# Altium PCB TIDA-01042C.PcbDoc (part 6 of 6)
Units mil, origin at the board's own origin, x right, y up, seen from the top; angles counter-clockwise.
Board outline 8300 x 7100 mil, 8 copper layers (Top Layer, Signal Layer 1, Signal Layer 2, Signal Layer 3, Signal Layer 4, Signal Layer 5, Signal Layer 6, Bottom Layer), stack 59.2 mil thick; 551 components, 303 nets, 1611 pads, 2322 vias.
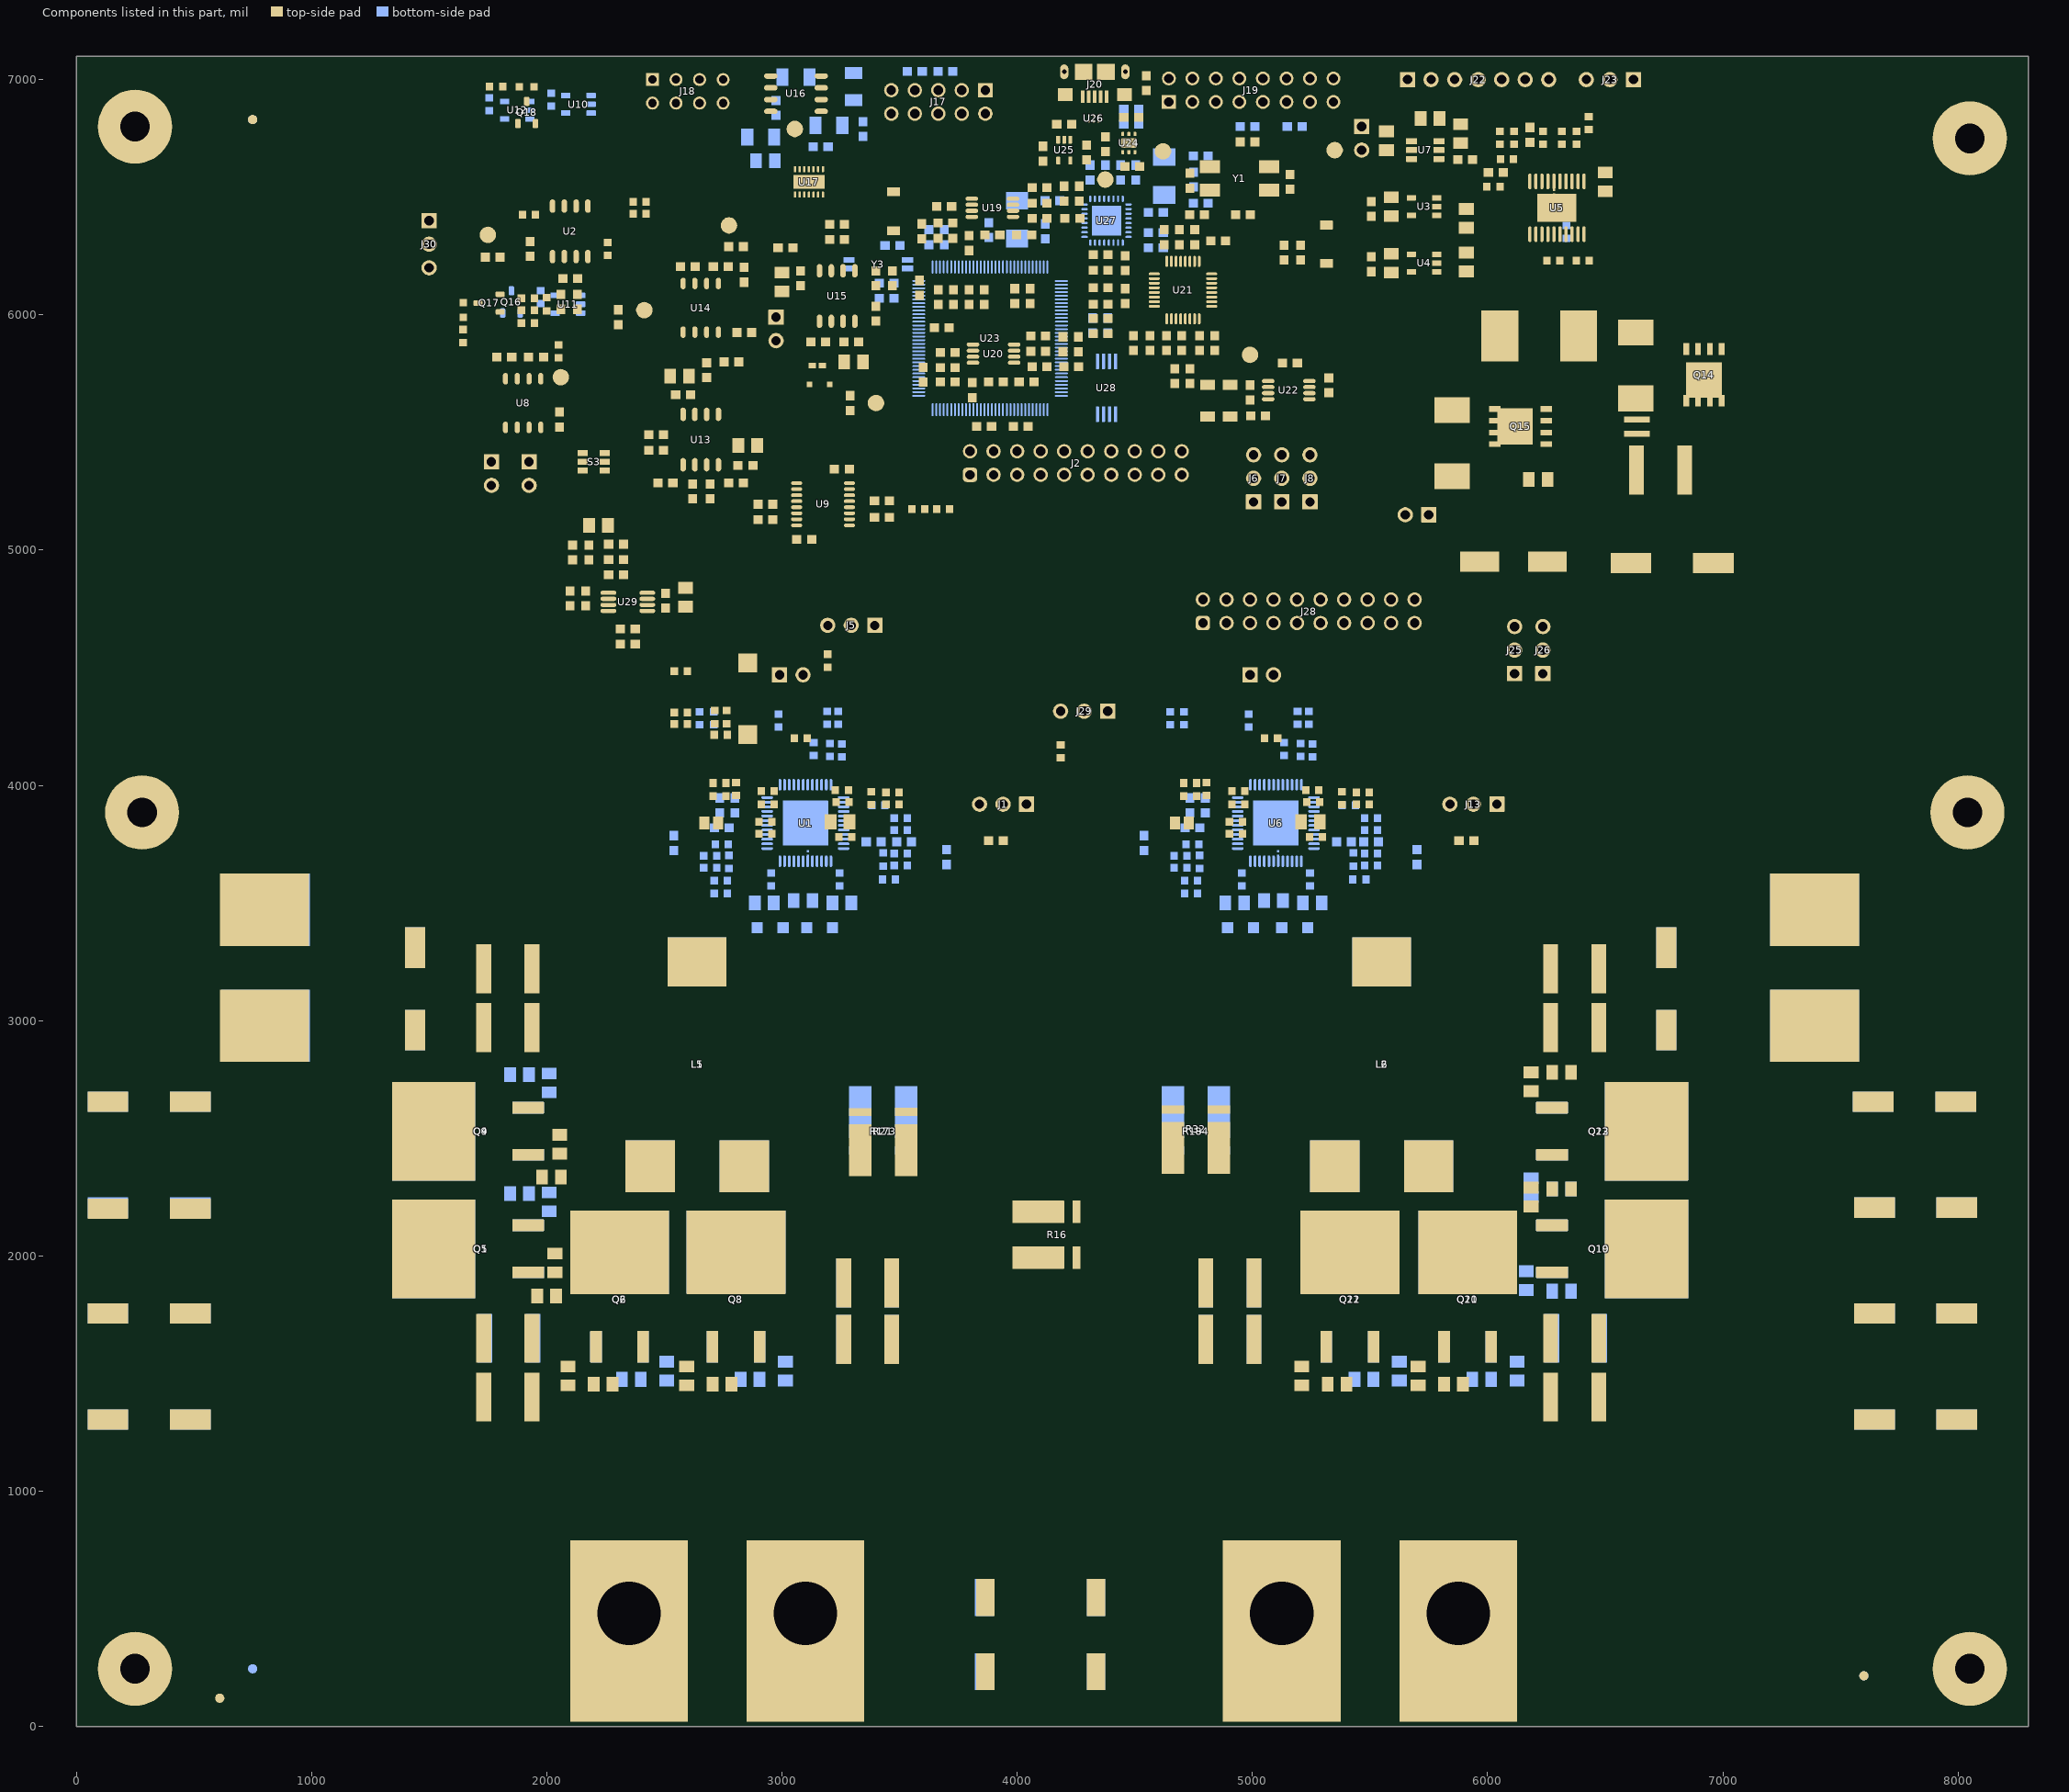
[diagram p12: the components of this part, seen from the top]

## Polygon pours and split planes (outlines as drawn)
V_HV on Bottom Layer "V_HV_L08_P6363" (solid, remove dead copper, pour order 6363): 7845,1090 6365,1090 6365,3125 7845,3125
V_HV on Bottom Layer "V_HV_L08_P6364" (solid, remove dead copper, pour order 6364): 1840,1095 335,1095 335,3130 1840,3130
I_TOTAL on Bottom Layer "I_TOTAL_L08_P6361" (solid, remove dead copper, pour order 6361): 4730,2090 3460,2090 3460,2815 4730,2815
PGND on Bottom Layer "PGND_L08_P6367" (solid, remove dead copper, pour order 6367): 1.9,0 1.9,7129.1 8321.9,7129.1 8321.9,0
AGND on Bottom Layer "AGND_L08_P6365" (solid, remove dead copper, pour order 6365): 2469.97,7080 1425,7080 1425,3650 6615,3650 6615,7080
V_LV on Bottom Layer "V_LV_L08_P6362" (solid, remove dead copper, pour order 6362): 5465.14,25.26 4829.74,25.26 4445,410 3750,410 3423.14,736.86 3423.14,2050 4888.14,2050 4888.14,1315 5465.14,738
AGND on Bottom Layer "AGND_L08_P6355" (solid, remove dead copper, pour order 6355): 4739.81,3520 4739.81,4004.81 4895,4160 5465,4160 5465,3565 5590,3565 5590,4270 4615,4270 4615,3520
AGND on Bottom Layer "AGND_L08_P6356" (solid, remove dead copper, pour order 6356): 2739.81,3520 2739.81,4004.81 2895,4160 3465,4160 3465,3565 3590,3565 3590,4270 2615,4270 2615,3520
SW4 on Bottom Layer "SW4_L08_P6359" (solid, remove dead copper, pour order 6359): 5520,2730 5520,2270 5483.67,2233.67 5103.67,2233.67 5070,2200 5070,1855 5111.33,1813.67 6313.67,1813.67 6350,1850 6350,2740 6316.33,2773.67 5563.67,2773.67
SW3 on Bottom Layer "SW3_L08_P6360" (solid, remove dead copper, pour order 6360): 3180,1855 3180,2185 3130,2235 2715,2235 2670.56,2279.44 2670.56,2714.44 2620,2765 1885,2765 1850.56,2730.56 1850.56,1879.44 1925,1805 3130,1805
NetL5_1 on Bottom Layer "NETL5_1_L08_P6357" (solid, remove dead copper, pour order 6357): 2720,2260 3370,2260 3395,2285 3395,2725 3370,2750 2720,2750 2700,2730 2700,2280
NetL6_2 on Bottom Layer "NETL6_2_L08_P6358" (solid, remove dead copper, pour order 6358): 4830,2250 5460,2250 5490,2280 5490,2730 5460,2760 4830,2760 4800,2730 4800,2280
I_TOTAL on Signal Layer 1 "I_TOTAL_L02_P6323" (solid, remove dead copper, pour order 6323): 4730,2090 3460,2090 3460,2815 4730,2815
V_LV on Signal Layer 1 "V_LV_L02_P6324" (solid, remove dead copper, pour order 6324): 3775,1860 4530,1860 4530,955 3775,955
PGND on Signal Layer 1 "PGND_L02_P6326" (solid, remove dead copper, pour order 6326): 0,0 0,7100 8300,7100 8300,0
AGND on Signal Layer 1 "AGND_L02_P6325" (solid, remove dead copper, pour order 6325): 2469.97,7080 1425,7080 1425,3650 6615,3650 6615,7080
V_LV on Signal Layer 2 "V_LV_L03_P6330" (solid, remove dead copper, pour order 6330): 5465.14,25.26 4829.74,25.26 4445,410 3750,410 3423.14,736.86 3423.14,2050 4888.14,2050 4888.14,1315 5465.14,738
I_TOTAL on Signal Layer 2 "I_TOTAL_L03_P6327" (solid, remove dead copper, pour order 6327): 4730,2085 3460,2085 3460,2810 4730,2810
V_LV on Signal Layer 2 "V_LV_L03_P6329" (solid, remove dead copper, pour order 6329): 3750,1855 4525,1855 4525,955 3750,955
PGND on Signal Layer 2 "PGND_L03_P6334" (solid, remove dead copper, pour order 6334): 0,0 0,7100 8300,7100 8300,0
AGND on Signal Layer 2 "AGND_L03_P6333" (solid, remove dead copper, pour order 6333): 2469.97,7080 1425,7080 1425,3650 6615,3650 6615,7080
V_HV on Signal Layer 2 "V_HV_L03_P6332" (solid, remove dead copper, pour order 6332): 7080,4800 6850,4800 6850,5105 6800,5155 6800,5500 6800,5525 6775,5550 6775,5820 7080,5820
V_HV on Signal Layer 2 "V_HV_L03_P6331" (solid, remove dead copper, pour order 6331): 7080,4800 6850,4800 6850,5105 6800,5155 6800,5500 6800,5525 6775,5550 6775,5820 7080,5820
PGND on Top Layer "PGND_L01_P6322" (solid, remove dead copper, pour order 6322): 1.9,0 1.9,7129.1 8321.9,7129.1 8321.9,0
AGND on Top Layer "AGND_L01_P6321" (solid, remove dead copper, pour order 6321): 2469.97,7080 1425,7080 1425,3650 6615,3650 6615,7080
V_LV on Top Layer "V_LV_L01_P6318" (solid, remove dead copper, pour order 6318): 5462,25.26 4824.74,25.26 4435,415 3745,415 3420,740 3420,2055 4885,2055 4885,1290 5462,713
NetC42_1 on Top Layer "NETC42_1_L01_P6308" (solid, remove dead copper, pour order 6308): 5715,4855 5715,5370 6200,5370 6200,5245 6200,5185 6070,5055 6065,5050 6065,4855
V_HV on Top Layer "V_HV_L01_P6312" (solid, remove dead copper, pour order 6312): 7050,4800 6870,4800 6850,4820 6850,5104.74 6799.74,5155 6799.74,5500 6799.74,5525 6774.74,5550 6774.74,5784.74 6810,5820 7050,5820 7079.74,5790.26 7079.74,4829.74
NetD6_2 on Top Layer "NETD6_2_L01_P6309" (solid, remove dead copper, pour order 6309): 6215,5430 6215.01,5729.99 6150,5795 6150,6015 6115,6050 6000,6050 5957.5,6007.5 5957.5,5822.5 5935,5800 5790,5800 5750,5760 5750,5430 5780,5400 6185,5400
NetC41_1 on Top Layer "NETC41_1_L01_P6307" (solid, remove dead copper, pour order 6307): 6295,5810 6295,6020 6330,6055 7060,6055 7080,6035 7080,5865 7055,5840 6800,5840 6740,5780 6705,5780 6325,5780
SW1 on Top Layer "SW1_L01_P6317" (solid, remove dead copper, pour order 6317): 3180,1840 3180,2200 3143.26,2236.74 2716.74,2236.74 2670,2283.49 2670,2750 2653.26,2766.74 1886.74,2766.74 1850,2730 1850,1845 1888.26,1806.74 3146.74,1806.74
NetL1_2 on Top Layer "NETL1_2_L01_P6313" (solid, remove dead copper, pour order 6313): 2720,2270 3370,2270 3395,2295 3395,2735 3370,2760 2720,2760 2700,2740 2700,2290
V_HV on Top Layer "V_HV_L01_P6320" (solid, remove dead copper, pour order 6320): 1840,1095 335,1095 335,3130 1840,3130
V_HV on Top Layer "V_HV_L01_P6319" (solid, remove dead copper, pour order 6319): 7845,1090 6365,1090 6365,3125 7845,3125
SW2 on Top Layer "SW2_L01_P6316" (solid, remove dead copper, pour order 6316): 5520,2730 5520,2280 5473.67,2233.67 5108.67,2233.67 5070,2195 5070,1860 5116.33,1813.67 6308.67,1813.67 6350,1855 6350,2740 6316.33,2773.67 5563.67,2773.67
NetL2_1 on Top Layer "NETL2_1_L01_P6314" (solid, remove dead copper, pour order 6314): 4830,2260 5460,2260 5490,2290 5490,2740 5460,2770 4830,2770 4800,2740 4800,2290
DGND on Top Layer "DGND_L01_P6311" (solid, remove dead copper, pour order 6311): 4155,7025 4150,7020 4150,6610 4280,6610 4265,6595 4265,6285 4275,6275 4535,6275 4535,6585 4570,6620 4570,7025 4170,7025 4165,7030
DGND on Top Layer "DGND_L01_P6310" (solid, remove dead copper, pour order 6310): 4150,7000 4150,6600 4250,6600 4250,6250 4500,6250 4500,6495 4575,6495 4570,6500 4570,7000
I_TOTAL on Top Layer "I_TOTAL_L01_P6315" (solid, remove dead copper, pour order 6315): 4730,2090 3460,2090 3460,2815 4730,2815
I_TOTAL on Signal Layer 3 "I_TOTAL_L04_P6335" (solid, remove dead copper, pour order 6335): 4730,2090 3460,2090 3460,2815 4730,2815
V_LV on Signal Layer 3 "V_LV_L04_P6338" (solid, remove dead copper, pour order 6338): 3770,1855 4520,1855 4520,955 3770,955
AGND on Signal Layer 3 "AGND_L04_P6340" (solid, remove dead copper, pour order 6340): 2469.97,7080 1285,7080 1285,3650 6615,3650 6615,7080
PGND on Signal Layer 3 "PGND_L04_P6341" (solid, remove dead copper, pour order 6341): 5797.48,7075 7280,7075 7280,3545 0,3545 0,7075 2472.33,7075 1485,7075 1485,5485 2487.75,5485 3627.33,4345.42 3630.03,4348.12 4646.91,4348.12 4646.91,4350 5795.11,5498.19
V_HV on Signal Layer 3 "V_HV_L04_P6339" (solid, remove dead copper, pour order 6339): 0,0 0,3525 8300,3525 8300,0
V_HV on Signal Layer 3 "V_HV_L04_P6336" (solid, remove dead copper, pour order 6336): 7080,4795 6850,4795 6850,5100 6800,5150 6800,5495 6800,5520 6775,5545 6775,5815 7080,5815
V_HV on Signal Layer 3 "V_HV_L04_P6337" (solid, remove dead copper, pour order 6337): 8300,3430 6850,3430 6850,5105 6800,5155 6800,5500 6800,5525 6775,5550 6775,5820 8300,5820
V_LV on Signal Layer 4 "V_LV_L05_P6342" (solid, remove dead copper, pour order 6342): 3770,1855 4520,1855 4520,955 3770,955
PGND on Signal Layer 4 "PGND_L05_P6346" (solid, remove dead copper, pour order 6346): 0,0 0,7960 8300,7960 8300,0
AGND on Signal Layer 4 "AGND_L05_P6345" (solid, remove dead copper, pour order 6345): 2469.97,7080 1425,7080 1425,3650 6615,3650 6615,7080
V_HV on Signal Layer 4 "V_HV_L05_P6343" (solid, remove dead copper, pour order 6343): 7074.74,4802.72 6844.74,4802.72 6844.74,5107.72 6794.74,5157.72 6794.74,5502.72 6794.74,5527.72 6769.74,5552.72 6769.74,5822.72 7074.74,5822.72
DGND on Signal Layer 4 "DGND_L05_P6344" (solid, remove dead copper, pour order 6344): 4100,7000 4100,6850 3990,6850 3975,6835 3975,6800 3400,6800 3350,6750 3350,6650 3200,6650 3200,5475 4700,5475 4700,5550 4700,6200 4900,6200 4900,6350 5050,6350 5050,6850 4600,6850 4600,7000
I_TOTAL on Signal Layer 6 "I_TOTAL_L07_P6351" (solid, remove dead copper, pour order 6351): 4730,2090 3460,2090 3460,2815 4730,2815
V_LV on Signal Layer 6 "V_LV_L07_P6352" (solid, remove dead copper, pour order 6352): 3770,1850 4520,1850 4520,955 3770,955
PGND on Signal Layer 6 "PGND_L07_P6354" (solid, remove dead copper, pour order 6354): 0,0 0,7100 8300,7100 8300,0
AGND on Signal Layer 6 "AGND_L07_P6353" (solid, remove dead copper, pour order 6353): 2469.97,7080 1425,7080 1425,3650 6615,3650 6615,7080
V_LV on Signal Layer 5 "V_LV_L06_P6347" (solid, remove dead copper, pour order 6347): 3775,1860 4530,1860 4530,955 3775,955
PGND on Signal Layer 5 "PGND_L06_P6350" (solid, remove dead copper, pour order 6350): 0,-1865 0,7100 8300,7100 8300,-1865
AGND on Signal Layer 5 "AGND_L06_P6348" (solid, remove dead copper, pour order 6348): 2469.97,7080 1425,7080 1425,3650 6615,3650 6615,7080
V_HV on Signal Layer 5 "V_HV_L06_P6349" (solid, remove dead copper, pour order 6349): 8300,0 0,0 0,3265 8300,3265

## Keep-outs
Keep-Out Layer:
  the board outline again, w10
  text ".Layer_Name" at -823,-6358.49 h60

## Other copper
Top Layer:
  rectangle net NetD7_2: 6580,5555 6690,5605
  rectangle net PGND: 6215,6395 6535,6520
  rectangle net V_HV: 1650,3080 1840,3350
  region net V_HV: 335,1135 330,1130 330,555 815,50 2695,50 2695,1135
  region net PGND: 3395,740 3735,400 4435,400 4790,45 3395,45
  pour cut-out: 3780,2135 3780,2045 4395,2045 4395,2135
  pour cut-out: 4800,2260 4730,2260 4730,2770 4800,2770
  region net PGND: 6150,4855 6700,4855 6700,5455 6325,5455 6275,5405 6225,5355 6225,5055 6200,5030 6150,5030
  region net V_HV: 7030,4600 7030,5150 6850,5330 6850,5430 7210,5430 7210,4600
  pour cut-out: 2035,-45 2035,850 2670,850 2670,-45
  pour cut-out: 6230.97,6280.64 6220,6280.64 6220,6385 6236.74,6385 6245,6376.74 6245,6294.67
  pour cut-out: 6200,6285 6220,6285 6230,6275 6230,6255 6220,6245 6200,6245 6190,6255 6190,6275
  pour cut-out: 6625,5520 6645,5520 6655,5510 6655,5490 6645,5480 6625,5480 6615,5490 6615,5510
  pour cut-out: 3460,2270 3395,2270 3395,2755 3460,2755
  text ".Layer_Name" at -823,-6358.49 h60
Signal Layer 1:
  pour cut-out: 6200,6285 6220,6285 6230,6275 6230,6255 6220,6245 6200,6245 6190,6255 6190,6275
  pour cut-out: 6625,5520 6645,5520 6655,5510 6655,5490 6645,5480 6625,5480 6615,5490 6615,5510
  text ".Layer_Name" at -825,-6355 h60
Signal Layer 2:
  pour cut-out: 6200,6285 6220,6285 6230,6275 6230,6255 6220,6245 6200,6245 6190,6255 6190,6275
  pour cut-out: 6625,5520 6645,5520 6655,5510 6655,5490 6645,5480 6625,5480 6615,5490 6615,5510
  text ".Layer_Name" at -825,-6355 h60
Signal Layer 3:
  rectangle net AGND: 3000,3735 3205,3940
  rectangle net AGND: 5000,3735 5200,3940
  rectangle net I_TOTAL: 3570,2165 4605,2815
  pour cut-out: 6200,6285 6220,6285 6230,6275 6230,6255 6220,6245 6200,6245 6190,6255 6190,6275
  pour cut-out: 6625,5520 6645,5520 6655,5510 6655,5490 6645,5480 6625,5480 6615,5490 6615,5510
  text ".Layer_Name" at -825,-6355 h60
Signal Layer 4:
  rectangle net I_TOTAL: 3570,2165 4330,2815
  rectangle net I_TOTAL: 4400,2165 4560,2815
  pour cut-out: 6200,6285 6220,6285 6230,6275 6230,6255 6220,6245 6200,6245 6190,6255 6190,6275
  pour cut-out: 6625,5520 6645,5520 6655,5510 6655,5490 6645,5480 6625,5480 6615,5490 6615,5510
  region: 1720,2442.56
  text ".Layer_Name" at -825,-6355 h60
Signal Layer 5:
  pour cut-out: 6200,6285 6220,6285 6230,6275 6230,6255 6220,6245 6200,6245 6190,6255 6190,6275
  region net I_TOTAL: 3980,2165 3575,2165 3575,2815 3980,2815
  region net I_TOTAL: 4020,2815 4020,2165 4575,2165 4575,2815
  text ".layer_Name" at -820,-6360 h60
Signal Layer 6:
  pour cut-out: 6200,6285 6220,6285 6230,6275 6230,6255 6220,6245 6200,6245 6190,6255 6190,6275
  text ".layer_Name" at -820,-6360 h60
Bottom Layer:
  rectangle net AGND: 3082.61,3723.07 3142.61,3748.07
  rectangle net AGND: 5082.61,3723.07 5142.61,3748.07
  pour cut-out: 3780,2135 3780,2045 4395,2045 4395,2135
  region net PGND: 3395,740 3735,400 4435,400 4790,45 3395,45
  pour cut-out: 4800,2260 4730,2260 4730,2770 4800,2770
  pour cut-out: 3460,2270 3395,2270 3395,2755 3460,2755
  pour cut-out: 6200,6285 6220,6285 6230,6275 6230,6255 6220,6245 6200,6245 6190,6255 6190,6275
  pour cut-out: 6625,5520 6645,5520 6655,5510 6655,5490 6645,5480 6625,5480 6615,5490 6615,5510
  region net V_LV: 3922.5,1290 4297.5,1290 4297.5,1945 3922.5,1945
  text ".Layer_Name" at -823,-6358.49 h60
Multi-Layer:
  region: 1670,2642.56

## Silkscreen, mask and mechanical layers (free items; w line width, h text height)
Top Overlay:
  rectangle: 1355,4940 1655,5040
  lines w8: 2785,3890 2840,3890 2855,3875 ; 2855,3875 2855,3884.89 2845.11,3875 2855,3875
  text "BUCK MODE" at 1635,7025 h28
  text "AGND" at 6730,6985 h72.83
  text "RESET" at 5600,6915 h40
  text "TDO" at 5725,6915 h40
  text "TDI" at 5830,6915 h40
  text "TMS" at 5925,6915 h40
  text "TCK" at 6025,6915 h40
  text "RX" at 6135,6915 h40
  text "TX" at 6240,6915 h40
  text "IREF" at 2380,6875 h72.83 r90
  text "VREF" at 2865,6865 h72.83 r90
  text "MISO" at 4605,6820 h40
  text "MOSI" at 4705,6820 h40
  text "CS" at 4820,6820 h40
  text "SCLK" at 4895,6820 h40
  text "DRDY" at 4995,6820 h40
  text "DONE" at 5100,6820 h40
  text "AGND" at 5205,6820 h40
  text "AGND" at 5315,6820 h35
  text "AGND" at 1435,6200 h72.83 r90
  text "CC" at 2955,5965 h28
  text "BOOST MODE" at 1555,5820 h28 r90
  text "V5A" at 1625,5725 h28 r90
  text "N" at 5365,5390 h28 r90
  text "BOOST" at 4910,5330 h28 r90
  text "NFAULT" at 3830,5230 h40
  text "SYNCOUT" at 4015,5230 h40
  text "ISETA" at 4250,5230 h40
  text "UVLO" at 4455,5230 h40
  text "OVPA" at 4655,5230 h40
  text "OPT" at 3750,5200 h40
  text "OVPB" at 4555,5200 h40
  text "IOUT2" at 4155,5195 h40
  text "SYNCIN" at 4330,5195 h40
  text "Y" at 5365,5195 h28 r90
  text "IOUT1" at 3955,5190 h40
  text "CV" at 1740,5165 h28
  text "BUCK" at 4910,5160 h28 r90
  text "VLV" at 1940,5125 h28 r90
  text "VHV" at 2095,5120 h28 r90
  text "DIR" at 4970,5080 h28
  text "EN1" at 5090,5080 h28
  text "EN2" at 5205,5080 h28
  text "V10-Aux" at 5600,5035 h28
  text "OPT" at 3025,4930 h28
  text "NFAULT2" at 4820,4600 h40
  text "SYNCOUT2" at 5005,4600 h40
  text "ISETA" at 5240,4600 h40
  text "UVLO" at 5445,4600 h40
  text "OVPA2" at 5645,4600 h40
  text "SYNC_OUT" at 2920,4590 h28
  text "IOUT4" at 5145,4565 h40
  text "SYNCIN2" at 5320,4565 h40
  text "OPT2" at 4740,4560 h40
  text "IOUT3" at 4945,4560 h40
  text "OVPB2" at 5545,4560 h40
  text "EN3" at 6080,4350 h28
  text "EN4" at 6195,4350 h28
  text "LV" at 5800,3995 h28
  text "HV" at 6020,3995 h28
  text "LV" at 3790,3990 h28
  text "UVLO" at 3885,3990 h28
  text "HV" at 4040,3990 h28
  text "V_HV" at 2575,950 h80
  text "+" at 2300,925 h120
  text "-" at 3050,925 h120
  text "+" at 5025,925 h120
  text "V_LV" at 5300,925 h80
  text "-" at 5825,905 h120
  text ".Layer_Name" at -823,-6358.49 h60
Bottom Overlay:
  text "J3" at 4150,5165 h28
  text "J5" at 3150,5020 h28
  text "OPT" at 3110,4930 h28
  text "J21" at 5210,4520 h28
  text "HV BIAS LV" at 6065,3995 h28
  text "HV VIN LV" at 4060,3990 h28
  text "J1" at 4155,3900 h28
  text "V_HV" at 2870,955 h80
  text "+" at 2380,930 h120
  text "V_LV" at 5595,930 h80
  text "+" at 5105,925 h120
  text "-" at 3130,920 h120
  text "-" at 5910,900 h120
  text ".Layer_Name" at -823,-6358.49 h60
Top Paste:
  text ".Layer_Name" at -823,-6358.49 h60
Bottom Paste:
  text ".Layer_Name" at -823,-6358.49 h60
Top Solder:
  text ".Layer_Name" at -823,-6358.49 h60
  text ".Layer_Name" at -823,-6358.49 h60
Bottom Solder:
  text ".Layer_Name" at -823,-6358.49 h60
Drill Guide:
  text ".Layer_Name" at -823,-6358.49 h60
M1 Board Outline:
  the board outline again, w10
  text ".Layer_Name" at -823,-6358.49 h60
M2 Board Dimensions:
  rectangle: -1400,-5775 -1275,-5650
  rectangle: -1275,-5900 -900,-5775
  lines w7: -1400,-5775 -400,-5775 ; -1275,-5900 -1275,-5650 ; -1150,-5900 -1150,-5650 ; -900,-5900 -900,-5650 ; -650,-5900 -650,-5650 ; -1400,-5900 -400,-5900 -400,-5650 -1400,-5650 -1400,-5900
  text ".Layer_Name" at -823,-6358.49 h60
M3 3D STEP Top:
  text ".Layer_Name" at -823,-6358.49 h60
M4 3D STEP Bottom:
  text ".Layer_Name" at -823,-6358.49 h60
M5 Assembly Top:
  lines w10: -1692,-6430.17 4908,-6430.17 ; -1692,-6226.83 4910,-6226.83 ; -1692,-6023.5 -1692,-6633.5 2313,-6633.5 4910,-6633.5 4910,-6023.5 -1691.5,-6023.5 -1691.5,-6633.5 -116,-6633.5 ; 773,-6633.5 773,-6023.5 ; 2040,-6226.83 2040,-6023.5 ; 2880,-6226.83 2880,-6023.5 ; 3502,-6640 3502,-6437.17
  text "COMPONENTS MARKED 'DNP' SHOULD NOT BE POPULATED." at -246.5,-5818.5 h60
  text "ASSEMBLY VARIANT:" at -247,-5934 h60
  text ".VariantName" at 789,-5934 h60
  text "PCB VIEWED FROM TOP SIDE" at -1628.5,-6155.67 h60
  text "BOARD #:" at 848,-6155.67 h60
  text ".PRJ_Number" at 1393.5,-6155.67 h60
  text "REV:" at 2238,-6155.67 h60
  text ".PCB_Rev" at 2529.5,-6155.67 h60
  text ".VersionControl_RevNumber" at 3582,-6155.67 h60
  text "SVN REV:" at 2313.19,-6196.26 h60
  text "PLOT NAME =" at -1628.5,-6564.34 h60
  text ".plot_File_Name" at -823,-6564.34 h60
  text "GENERATED    :" at 850,-6564.34 h60
  text ".Print_Date" at 1719.5,-6564.34 h60
  text ".Print_Time" at 2448.5,-6564.34 h60
  text "TEXAS INSTRUMENTS" at 3713,-6564.34 h60
M6 Assembly Bottom:
  lines w10: -1692.5,-6227.33 4909.5,-6227.33 ; -1690.5,-6430.67 4909.5,-6430.67 ; -284.5,-6640.5 -284.5,-6437.67 ; 337.5,-6227.33 337.5,-6024 ; 1177.5,-6227.33 1177.5,-6024 ; 2444.5,-6634 2444.5,-6024 ; 3333.5,-6634 4909,-6634 4909,-6024 -1692.5,-6024 -1692.5,-6634 904.5,-6634 4909.5,-6634 4909.5,-6024
  text "COMPONENTS MARKED 'DNP' SHOULD NOT BE POPULATED." at 4702,-5818 h60
  text ".VariantName" at 3658,-5934 h60
  text "ASSEMBLY VARIANT:" at 4697,-5934 h60
  text ".VersionControl_RevNumber" at -364.5,-6156.17 h60
  text "SVN REV:" at 141.5,-6156.17 h60
  text ".PCB_Rev" at 688,-6156.17 h60
  text "REV:" at 979.5,-6156.17 h60
  text ".PRJ_Number" at 1824,-6156.17 h60
  text "BOARD #:" at 2369.5,-6156.17 h60
  text "PCB VIEWED FROM BOTTOM SIDE" at 4846,-6156.17 h60
  text "TEXAS INSTRUMENTS" at -495.5,-6564.84 h60
  text ".Print_Time" at 769,-6564.84 h60
  text ".Print_Date" at 1498,-6564.84 h60
  text "GENERATED    :" at 2367.5,-6564.84 h60
  text ".plot_File_Name" at 4040.5,-6564.84 h60
  text "PLOT NAME =" at 4846,-6564.84 h60
M9 Title Sheet:
  drawing of 57 lines, arcs and shapes, not listed
  text "1" at -660.16,2536.5 h70
  text "2" at 1835.5,2536.5 h70
  text "3" at 4324.84,2536.5 h70
  text "4" at 4831.51,2536.5 h70
  text "5" at 7330.5,2536.5 h70
  text "6" at 9835.5,2536.5 h70
  text "A" at -1816.5,1393.5 h70
  text "A" at 12983.5,1393.5 h70
  text "B" at -1816.5,-986.5 h70
  text "B" at 12983.5,-986.5 h70
  text "C" at -1816.5,-3361.5 h70
  text "C" at 12983.5,-3361.5 h70
  text "PROJECT TITLE:" at 9943.5,-5222.5 h45
  text ".PRJ_Title" at 9993.5,-5355.83 h70
  text "DESIGNED FOR:" at 9943.5,-5523.5 h45
  text ".PRJ_Customer" at 9993.5,-5663.5 h70
  text "D" at -1816.5,-5731.5 h70
  text "D" at 12983.5,-5731.5 h70
  text "FILE NAME:" at 9943.5,-5823.5 h45
  text ".PCB_File_Name_No_Path" at 9993.5,-5943.5 h70
  text "Texas Instruments (TI) and/or its licensors do not warrant the accuracy or completeness of this specification" at 4974,-6105.34 h45
  text "ENGINEER:" at 9943.5,-6113.5 h45
  text "LAYOUT BY:" at 11448.5,-6113.5 h45
  text "or any information contained therein. TI and/or its licensors do not warrant that this design will meet" at 4929.01,-6218 h45
  text ".PRJ_Engineer" at 9993.5,-6268.49 h70
  text ".PCB_Layout" at 11499,-6268.49 h70
  text "the specifications, will be suitable for your application or fit for any particular purpose, or will operate in" at 4929.01,-6330.67 h45
  text ".Layer_Name" at -823,-6358.49 h60
  text "ALTIUM DESIGNER VERSION:" at 11448.5,-6423.5 h45
  text "an implementation. TI and/or its licensors do not warrant that the design is production worthy. You should" at 4929.01,-6443.33 h45
  text "completely validate and test your design implementation to confirm the system functionality for your application." at 4974,-6556 h45
  text ".print_Scale" at 9993.5,-6556.83 h70
  text ".Application_BuildNumber" at 11499,-6556.83 h70
  text "1" at -660.16,-6763.5 h70
  text "2" at 1835.5,-6763.5 h70
  text "3" at 4324.84,-6763.5 h70
  text "4" at 6831.51,-6763.5 h70
  text "5" at 9330.5,-6763.5 h70
  text "6" at 11835.5,-6763.5 h70
M10 Fab Notes:
  drawing of 185 lines, arcs and shapes, not listed
  text "DESIGN INFORMATION" at 10981.02,410 h60
  text "MIN. TRACK WIDTH:" at 10336.46,230 h60
  text "8" at 11432.7,230 h60
  text "MIL" at 11587.46,230 h60
  text "MIN. CLEARANCE:" at 10336.46,98 h60
  text "0.2" at 11372.7,98 h60
  text "mm" at 11587.46,98 h60
  text "MIN. VIA PAD SIZE:" at 10336.46,-34 h60
  text "24" at 11402.71,-34 h60
  text "MIL" at 11587.46,-34 h60
  text "0.05mm (2MIL)" at 11031.46,-175.71 h60
  text "MINIMUM ANNULAR RING" at 10007.23,-180 h60
  text "EXTERNAL" at 11739.46,-180 h60
  text "PER" at 10207.23,-298 h60
  text "IPC-D-275 CLASS 2 LEVEL C" at 10427.23,-298 h60
  text "MIL, HOLES" at 11915.46,-410.29 h60
  text "+/-" at 11523,-411 h60
  text "+/-" at 12377,-411 h60
  text "REGISTRATION TOLERANCES:" at 10007.23,-416 h60
  text "METAL" at 11207,-416 h60
  text "5" at 11783.2,-416 h60
  text "3" at 12616.2,-416 h60
  text "MIL" at 12732.46,-416 h60
  text "MATERIAL:" at 9932.46,-625.46 h60
  text "FR-4 High Tg" at 10918.9,-765.79 h60
  text "FR-408" at 10353.46,-774.36 h60
  text "X" at 10765.46,-774.36 h60
  text "OTHER" at 11841.46,-774.36 h60
  text "62 MIL (1.6mm) +/-10%" at 10673.56,-937.08 h60
  text "THICKNESS:" at 10007.23,-941.36 h60
  text "X" at 10545.4,-941.36 h60
  text "OTHER" at 11958.46,-941.36 h60
  text "TOLERANCE:" at 8862.23,-1099.36 h60
  text "X" at 10846.53,-1099.36 h60
  text "ANSI IPC-6012 TYPE 3 CLASS 2" at 11033.48,-1099.36 h60
  text "OTHER +/-" at 11033.46,-1255.36 h60
  text "BOW & TWIST:" at 10007.23,-1412.36 h60
  text "X" at 10846.53,-1412.36 h60
  text "ANSI IPC-6012 TYPE 3 CLASS 2" at 11033.48,-1412.36 h60
  text "OTHER +/-" at 11033.46,-1570.87 h60
  text "DRILLING:" at 9932.46,-1709.36 h60
  text "REFERENCE:" at 10007.23,-1826.36 h60
  text "X" at 10655.46,-1826.36 h60
  text "AS SHOWN" at 10842.46,-1826.36 h60
  text "X" at 11556.46,-1826.36 h60
  text "NC_DRILL FILES" at 11693.46,-1826.36 h60
  text "PTH MIN COPPER THICKNESS:" at 10007.23,-1984.36 h60
  text "X" at 11357.46,-1984.36 h60
  text "1MIL" at 11494.46,-1984.36 h60
  text "OTHER" at 11991.46,-1984.36 h60
  text "BOARD FINISH:" at 9932.46,-2143.36 h60
  text "SILKSCREEN:" at 10087.68,-2261.36 h60
  text "X" at 11036.46,-2261.36 h60
  text "TOP" at 11162.46,-2261.36 h60
  text "X" at 11546.46,-2261.36 h60
  text "BOTTOM" at 11673.46,-2261.36 h60
  text "SILKSCREEN COLOR:" at 10087.68,-2428.36 h60
  text "X" at 11035.42,-2428.36 h60
  text "WHITE" at 11162.46,-2428.36 h60
  text "OTHER" at 11673.46,-2428.36 h60
  text "SOLDER RESIST COLOR:" at 10087.68,-2598.36 h60
  text "X" at 10655.42,-2757.56 h60
  text "GREEN" at 10782.46,-2757.56 h60
  text "BLUE" at 11373.46,-2757.56 h60
  text "OTHER" at 11911.46,-2757.56 h60
  text "IMMERSION GOLD (ENIG)" at 10993.46,-2946.08 h60
  text "ENEPIG" at 12331,-2949.36 h60
  text "SURFACE FINISH:" at 9932.46,-2950.36 h60
  text "X" at 10805,-2955 h60
  text "IMM. TIN/SILVER OR EQUIV" at 10262,-3107.36 h60
  text "OTHER" at 11693.46,-3107.36 h60
  text "ARRAY/PANEL:" at 9932.46,-3286.36 h60
  text "CUT AND TRIM PER MECH LAYER 1" at 10993.46,-3290.65 h60
  text "N.C. ROUTE" at 10993.46,-3442.36 h60
  text "V. SCORE" at 11859.46,-3442.36 h60
  text "X" at 10800,-3445 h60
  text "CERTIFICATION:" at 9932.46,-3579.36 h60
  text "MATERIALS AND WORKMANSHIP FOR ALL PCBS" at 10657.46,-3579.36 h60
  text "TO MEET OR EXCEED THE REQUIREMENTS OF:" at 10657.46,-3677.36 h60
  text "X" at 10283.96,-3813.87 h60
  text "ANSI IPC-A-600F CLASS ->" at 10422.96,-3813.87 h60
  text "X" at 12062.02,-3813.87 h60
  text "2" at 12180.96,-3813.86 h60
  text "1" at 11865.96,-3815.36 h60
  text "3" at 12534.96,-3815.36 h60
  text "X" at 10286.02,-3973.36 h60
  text "UL 94V-0" at 10422.96,-3973.36 h60
  text "X" at 11098.02,-3973.36 h60
  text "RoHS" at 11234.96,-3973.36 h60
  text "OTHER" at 11879.36,-3973.36 h60
  text "PER ORDER" at 12276.42,-3973.36 h60
  text "ADDITIONAL REQUIREMENTS:" at 9932.46,-4114.36 h60
  text "MICROSECTION:" at 10007.23,-4229.36 h60
  text "YES" at 10912.96,-4229.36 h60
  text "REQUIRED" at 11774.46,-4385.51 h60
  text "BARE BOARD ELEC. TEST:" at 10007.23,-4388.36 h60
  text "NONE" at 11312.96,-4388.36 h60
  text "X" at 11647.46,-4388.36 h60
  text "PER ORDER" at 12366.46,-4388.36 h60
  text "MANUFACTURER'S UL:" at 10007.23,-4545.36 h60
  text "RAIL" at 11172.96,-4549.65 h60
  text "METAL" at 11664.77,-4549.65 h60
  text "X" at 12040,-4550 h60
  text "SILK" at 12176.46,-4549.65 h60
  text ".Layer_Name" at -823,-6358.49 h60
M11 Gerber Information:
  lines w10: -1692,-6430.17 4908,-6430.17 ; -1692,-6226.83 4910,-6226.83 ; -1692,-6023.5 -1692,-6633.5 2313,-6633.5 4910,-6633.5 4910,-6023.5 -1691.5,-6023.5 -1691.5,-6633.5 -116,-6633.5 ; 773,-6633.5 773,-6023.5 ; 2040,-6226.83 2040,-6023.5 ; 2880,-6226.83 2880,-6023.5 ; 3502,-6640 3502,-6437.17
  text "ALL ARTWORK VIEWED FROM TOP SIDE" at -1628.5,-6155.67 h60
  text "BOARD #:" at 848,-6155.67 h60
  text ".PRJ_Number" at 1393.5,-6155.67 h60
  text "REV:" at 2238,-6155.67 h60
  text ".PCB_Rev" at 2529.5,-6155.67 h60
  text ".VersionControl_RevNumber" at 3582,-6155.67 h60
  text "SVN REV:" at 2313.19,-6196.26 h60
  text "LAYER NAME =" at -1628.5,-6358.49 h60
  text "PLOT NAME =" at -1628.5,-6564.34 h60
  text ".plot_File_Name" at -823,-6564.34 h60
  text "GENERATED    :" at 850,-6564.34 h60
  text ".Print_Date" at 1719.5,-6564.34 h60
  text ".Print_Time" at 2448.5,-6564.34 h60
  text "TEXAS INSTRUMENTS" at 3713,-6564.34 h60
M12 Stackup:
  drawing of 503 lines, arcs and shapes, not listed
  text "Layer" at -484.42,10465 h60
  text "Name" at -74.51,10465 h60
  text "Material" at 865.23,10465 h60
  text "Thickness" at 1725,10465 h60
  text "Constant" at 2374.84,10465 h60
  text "Board Layer Stack" at 2944.7,10465 h60
  text "1" at -484.42,10345 h60
  text "Top Overlay" at -74.51,10345 h60
  text "2" at -484.42,10225 h60
  text "Top Solder" at -74.51,10225 h60
  text "Solder Resist" at 865.23,10225 h60
  text "0.40mil" at 1725,10225 h60
  text "3.5" at 2374.84,10225 h60
  text "3" at -484.42,10105 h60
  text "Top Layer" at -74.51,10105 h60
  text "Copper" at 865.23,10105 h60
  text "3.20mil" at 1725,10105 h60
  text "4" at -484.42,9985 h60
  text "Dielectric1" at -74.51,9985 h60
  text "FR-4" at 865.23,9985 h60
  text "5.00mil" at 1725,9985 h60
  text "4.8" at 2374.84,9985 h60
  text "5" at -484.42,9865 h60
  text "Signal Layer 1" at -74.51,9865 h60
  text "Copper" at 865.23,9865 h60
  text "2.80mil" at 1725,9865 h60
  text "6" at -484.42,9745 h60
  text "Dielectric 2" at -74.51,9745 h60
  text "FR-4" at 865.23,9745 h60
  text "5.00mil" at 1725,9745 h60
  text "4.2" at 2374.84,9745 h60
  text "7" at -484.42,9625 h60
  text "Signal Layer 2" at -74.51,9625 h60
  text "Copper" at 865.23,9625 h60
  text "2.80mil" at 1725,9625 h60
  text "8" at -484.42,9505 h60
  text "Dielectric 3" at -74.51,9505 h60
  text "FR-4" at 865.23,9505 h60
  text "5.00mil" at 1725,9505 h60
  text "4.2" at 2374.84,9505 h60
  text "9" at -484.42,9385 h60
  text "Signal Layer 3" at -74.51,9385 h60
  text "Copper" at 865.23,9385 h60
  text "2.80mil" at 1725,9385 h60
  text "10" at -484.42,9265 h60
  text "Dielectric4" at -74.51,9265 h60
  text "FR-4" at 865.23,9265 h60
  text "6.00mil" at 1725,9265 h60
  text "4.2" at 2374.84,9265 h60
  text "11" at -484.42,9145 h60
  text "Signal Layer 4" at -74.51,9145 h60
  text "Copper" at 865.23,9145 h60
  text "2.80mil" at 1725,9145 h60
  text "12" at -484.42,9025 h60
  text "Dielectric 5" at -74.51,9025 h60
  text "FR-4" at 865.23,9025 h60
  text "5.00mil" at 1725,9025 h60
  text "4.2" at 2374.84,9025 h60
  text "13" at -484.42,8905 h60
  text "Signal Layer 5" at -74.51,8905 h60
  text "Copper" at 865.23,8905 h60
  text "2.80mil" at 1725,8905 h60
  text "14" at -484.42,8785 h60
  text "Dielectric 6" at -74.51,8785 h60
  text "FR-4" at 865.23,8785 h60
  text "5.00mil" at 1725,8785 h60
  text "4.2" at 2374.84,8785 h60
  text "15" at -484.42,8665 h60
  text "Signal Layer 6" at -74.51,8665 h60
  text "Copper" at 865.23,8665 h60
  text "2.80mil" at 1725,8665 h60
  text "16" at -484.42,8545 h60
  text "Dielectric 7" at -74.51,8545 h60
  text "FR-4" at 865.23,8545 h60
  text "5.00mil" at 1725,8545 h60
  text "4.2" at 2374.84,8545 h60
  text "17" at -484.42,8425 h60
  text "Bottom Layer" at -74.51,8425 h60
  text "Copper" at 865.23,8425 h60
  text "3.20mil" at 1725,8425 h60
  text "18" at -484.42,8305 h60
  text "Bottom Solder" at -74.51,8305 h60
  text "Solder Resist" at 865.23,8305 h60
  text "0.40mil" at 1725,8305 h60
  text "3.5" at 2374.84,8305 h60
  text "19" at -484.42,8185 h60
  text "Bottom Overlay" at -74.51,8185 h60
  text ".Layer_Name" at -823,-6358.49 h60
M13 Component Bodies Top:
  text ".Layer_Name" at -823,-6358.49 h60
M14 Component Bodies Bottom:
  text ".Layer_Name" at -823,-6358.49 h60
M15 Courtyards Top:
  text ".Layer_Name" at -823,-6358.49 h60
M16 Courtyards Bottom:
  text ".Layer_Name" at -823,-6358.49 h60
Drill Drawing:
  circle w10: c5783.72,10329.32 r16.58
  circle w10: c5783.72,10329.32 r27.63
  circle w10: c5783.72,10080.68 r27.63
  lines w10: 5756.09,9182.82 5756.09,9196.63 5769.9,9210.44 5756.09,9224.26 5756.09,9238.07 5769.9,9238.07 5783.72,9224.26 5797.53,9238.07 5811.34,9238.07 5811.34,9224.26 5797.53,9210.44 5811.34,9196.63 5811.34,9182.82 5797.53,9182.82 5783.72,9196.63 5769.9,9182.82 5756.09,9182.82 ; 5756.09,9320.95 5769.9,9320.95 5769.9,9307.14 5797.53,9307.14 5797.53,9320.95 5811.34,9320.95 5811.34,9348.58 5797.53,9348.58 5797.53,9362.39 5769.9,9362.39 5769.9,9348.58 5756.09,9348.58 5756.09,9320.95 ; 5756.09,9445.27 5769.9,9445.27 5783.72,9431.46 5797.53,9445.27 5811.34,9445.27 5797.53,9459.08 5811.34,9472.9 5797.53,9472.9 5783.72,9486.71 5769.9,9472.9 5756.09,9472.9 5769.9,9459.08 5756.09,9445.27 ; 5756.09,9569.59 5769.9,9569.59 5769.9,9555.78 5797.53,9555.78 5797.53,9569.59 5811.34,9569.59 5811.34,9597.22 5797.53,9597.22 5797.53,9611.03 5769.9,9611.03 5769.9,9597.22 5756.09,9597.22 5756.09,9569.59 ; 5756.09,9680.1 5811.34,9680.1 5811.34,9735.35 5756.09,9735.35 5756.09,9680.1 ; 5756.09,9859.67 5811.34,9859.67 5783.72,9804.42 5756.09,9859.67 ; 5756.09,9928.74 5783.72,9942.55 5811.34,9928.74 5797.53,9956.36 5811.34,9983.99 5783.72,9970.18 5756.09,9983.99 5769.9,9956.36 5756.09,9928.74 ; 5756.09,10177.38 5811.34,10177.38 5811.34,10232.63 5756.09,10232.63 5756.09,10177.38 ; 5756.09,10577.96 5783.72,10550.34 5811.34,10577.96 5783.72,10605.59 5756.09,10577.96 ; 5756.09,10923.3 5756.09,10937.11 5769.9,10950.92 5756.09,10964.74 5756.09,10978.55 5769.9,10978.55 5783.72,10964.74 5797.53,10978.55 5811.34,10978.55 5811.34,10964.74 5797.53,10950.92 5811.34,10937.11 5811.34,10923.3 5797.53,10923.3 5783.72,10937.11 5769.9,10923.3 5756.09,10923.3 ; 5767.14,9575.12 5775.43,9575.12 5775.43,9566.83 5792.01,9566.83 5792.01,9575.12 5800.29,9575.12 5800.29,9591.69 5792.01,9591.69 5792.01,9599.98 5775.43,9599.98 5775.43,9591.69 5767.14,9591.69 5767.14,9575.12 ; 5767.14,10188.43 5800.29,10188.43 5800.29,10221.58 5767.14,10221.58 5767.14,10188.43 ; 5767.14,10934.35 5767.14,10942.64 5775.43,10950.92 5767.14,10959.21 5767.14,10967.5 5775.43,10967.5 5783.72,10959.21 5792.01,10967.5 5800.29,10967.5 5800.29,10959.21 5792.01,10950.92 5800.29,10942.64 5800.29,10934.35 5792.01,10934.35 5783.72,10942.64 5775.43,10934.35 5767.14,10934.35
  lines w12: 5706,9145.52 7684.19,9145.52 ; 5706,11010.32 7684.19,11010.32 ; 6043.86,9021.2 6043.86,11134.64 ; 6376.03,9021.2 6376.03,11134.64 ; 7012.59,9021.2 7012.59,11134.64 ; 7271.73,9021.2 7271.73,11134.64 ; 5706,9021.2 7684.19,9021.2 7684.19,11134.64 5706,11134.64 5706,9021.2
  text "Symbol" at 5780.59,11047.62 h72
  text "Quantity" at 6081.16,11047.62 h72
  text "Finished Hole Size" at 6413.33,11047.62 h72
  text "Plated" at 7049.89,11047.62 h72
  text "Hole Type" at 7309.03,11047.62 h72
  text "70" at 6081.16,10923.3 h60
  text "7.87mil (0.200mm)" at 6413.33,10923.3 h60
  text "PTH" at 7049.89,10923.3 h60
  text "Round" at 7309.03,10923.3 h60
  text "737" at 6081.16,10798.98 h60
  text "8.00mil (0.203mm)" at 6413.33,10798.98 h60
  text "PTH" at 7049.89,10798.98 h60
  text "Round" at 7309.03,10798.98 h60
  text "C" at 5755.31,10788.99 h55.25
  text "198" at 6081.16,10674.66 h60
  text "10.00mil (0.254mm)" at 6413.33,10674.66 h60
  text "PTH" at 7049.89,10674.66 h60
  text "Round" at 7309.03,10674.66 h60
  text "B" at 5755.31,10664.67 h55.25
  text "2" at 6081.16,10550.34 h60
  text "12.00mil (0.305mm)" at 6413.33,10550.34 h60
  text "PTH" at 7049.89,10550.34 h60
  text "Round" at 7309.03,10550.34 h60
  text "1310" at 6081.16,10426.02 h60
  text "16.00mil (0.406mm)" at 6413.33,10426.02 h60
  text "PTH" at 7049.89,10426.02 h60
  text "Round" at 7309.03,10426.02 h60
  text "A" at 5755.31,10416.03 h55.25
  text "2" at 6081.16,10301.7 h60
  text "20.00mil (0.508mm)" at 6413.33,10301.7 h60
  text "PTH" at 7049.89,10301.7 h60
  text "Round" at 7309.03,10301.7 h60
  text "3" at 6081.16,10177.38 h60
  text "28.00mil (0.711mm)" at 6413.33,10177.38 h60
  text "PTH" at 7049.89,10177.38 h60
  text "Round" at 7309.03,10177.38 h60
  text "8" at 6081.16,10053.06 h60
  text "35.43mil (0.900mm)" at 6413.33,10053.06 h60
  text "PTH" at 7049.89,10053.06 h60
  text "Round" at 7309.03,10053.06 h60
  text "16" at 6081.16,9928.74 h60
  text "39.37mil (1.000mm)" at 6413.33,9928.74 h60
  text "PTH" at 7049.89,9928.74 h60
  text "Round" at 7309.03,9928.74 h60
  text "94" at 6081.16,9804.42 h60
  text "40.00mil (1.016mm)" at 6413.33,9804.42 h60
  text "PTH" at 7049.89,9804.42 h60
  text "Round" at 7309.03,9804.42 h60
  text "10" at 6081.16,9680.1 h60
  text "40.16mil (1.020mm)" at 6413.33,9680.1 h60
  text "PTH" at 7049.89,9680.1 h60
  text "Round" at 7309.03,9680.1 h60
  text "6" at 6081.16,9555.78 h60
  text "125.98mil (3.200mm)" at 6413.33,9555.78 h60
  text "PTH" at 7049.89,9555.78 h60
  text "Round" at 7309.03,9555.78 h60
  text "4" at 6081.16,9431.46 h60
  text "254.00mil (6.452mm)" at 6413.33,9431.46 h60
  text "PTH" at 7049.89,9431.46 h60
  text "Round" at 7309.03,9431.46 h60
  text "4" at 6081.16,9307.14 h60
  text "270.00mil (6.858mm)" at 6413.33,9307.14 h60
  text "PTH" at 7049.89,9307.14 h60
  text "Round" at 7309.03,9307.14 h60
  text "2" at 6081.16,9182.82 h60
  text "19.69mil (0.500mm)" at 6413.33,9182.82 h60
  text "PTH" at 7049.89,9182.82 h60
  text "Slot" at 7309.03,9182.82 h60
  text "2466 Total" at 6081.16,9058.5 h60
  text "Slot definitions :" at 5780.59,8971.47 h60
  text "Routed Path Length" at 6231.31,8971.47 h60
  text "= Calculated from tool start centre position to tool end centre position." at 6771.05,8971.47 h60
  text "Hole Length" at 6231.31,8921.75 h60
  text "= Routed Path Length + Tool Size = Slot length as defined in the PCB layout" at 6571.25,8921.75 h60
  text ".Layer_Name" at -823,-6358.49 h60

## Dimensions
0,0 to 0,7100 on M2 Board Dimensions
0,0 to 8300,0 on M2 Board Dimensions
-1400,-5900 to -400,-5900 on M2 Board Dimensions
